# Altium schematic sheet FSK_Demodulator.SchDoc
size B
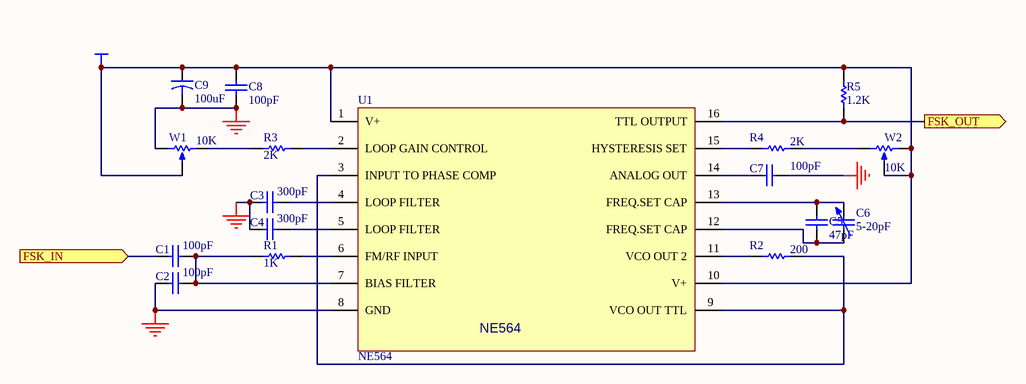
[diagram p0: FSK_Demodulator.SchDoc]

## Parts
C1  100pF  [RAD-0.3]
C2  100pF  [RAD-0.3]
C3  300pF  [RAD-0.3]
C4  300pF  [RAD-0.3]
C5  47pF  [RAD-0.3]
C6  5-20pF  [C3225-1210]
C7  100pF  [RAD-0.3]
C8  100pF  [RAD-0.3]
C9  100uF  [CAPR5-4X5]
R1  1K  [AXIAL-0.3]
R2  200  [AXIAL-0.3]
R3  2K  [AXIAL-0.3]
R4  2K  [AXIAL-0.3]
R5  1.2K  [AXIAL-0.3]
U1  NE564  [DIP-16]
W1  10K  [VR5]
W2  10K  [VR5]

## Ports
FSK_IN (in), FSK_OUT (out)

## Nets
+5: C8.2 C9.1 R5.2 U1.1(V+) U1.10(V+) W1.3(TAP) W2.2(BOT) W2.3(TAP)
GND: C2.1 C3.1 C4.1 C7.2 C8.1 C9.2 U1.8(GND) W1.1(TOP)
FSK_IN: C1.1 ; port FSK_IN
FSK_OUT: R5.1 U1.16(TTL_OUTPUT) ; port FSK_OUT
NetC1_2: C1.2 C2.2 R1.1 U1.7(BIAS_FILTER)
NetC3_2: C3.2 U1.4(LOOP_FILTER)
NetC4_2: C4.2 U1.5(LOOP_FILTER)
NetC5_1: C5.1 C6.1 U1.12(FREQ.SET_CAP)
NetC5_2: C5.2 C6.2 U1.13(FREQ.SET_CAP)
NetC7_1: C7.1 U1.14(ANALOG_OUT)
NetR1_2: R1.2 U1.6(FM/RF_INPUT)
NetR2_1: R2.1 U1.11(VCO_OUT_2)
NetR2_2: R2.2 U1.3(INPUT_TO_PHASE_COMP) U1.9(VCO_OUT_TTL)
NetR3_1: R3.1 W1.2(BOT)
NetR3_2: R3.2 U1.2(LOOP_GAIN_CONTROL)
NetR4_1: R4.1 U1.15(HYSTERESIS_SET)
NetR4_2: R4.2 W2.1(TOP)

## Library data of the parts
C1-C5 C7 C8 = Cap: Capacitor; Manufacturer: Generic Components; Class I: Passive
C6 = Cap Var: Variable or Adjustable Capacitor; Manufacturer: Generic Components; Class I: Passive
C9 = Cap2: Capacitor; Manufacturer: Generic Components; Class I: Passive
R1-R5 = Res1: Resistor; Manufacturer: Generic Components; Class I: Passive
U1 = NE564: Manufacturer: Philips; Class 1: PLL&DDS; Class 2: Phase Lock Loop
W1 W2 = RPot1: Potentiometer; Manufacturer: Generic Components; Class I: Passive; Set Position: 0.5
